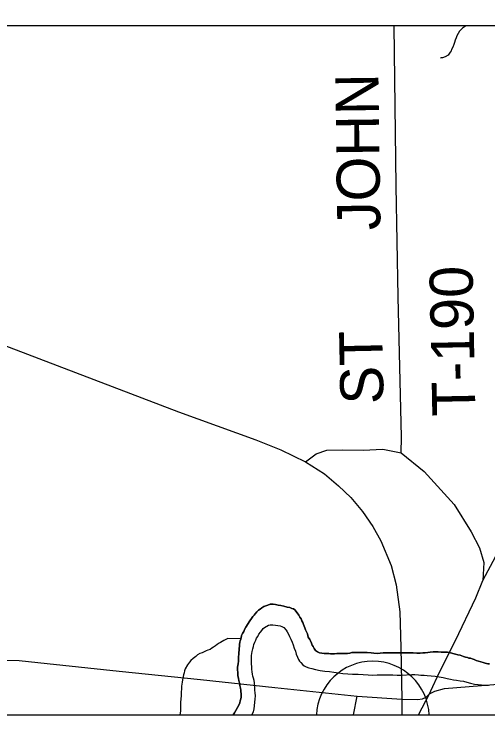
# Model space of a CAD drawing. Extents: x 0 to 34, y 0 to 22.
# Drawn here: x 3.825 to 4.449, y 14.1 to 15.024 of the extents above; entities that cross this region are included whole.
import ezdxf

# ---------------------------------------------------------------- set-up
doc = ezdxf.new("R2010")
doc.units = 0
for name, color, linetype in [('Default', 7, 'Continuous'), ('GM_X_Corporation', 7, 'Continuous'), ('GM_X_County_Road', 7, 'Continuous'), ('GM_X_Interchange_Ramps', 7, 'Continuous'), ('GM_X_Major_River', 7, 'Continuous'), ('GM_X_Minor_River', 7, 'Continuous'), ('GM_X_State_Route', 7, 'Continuous'), ('GM_X_Township_Road', 7, 'Continuous'), ('GM_X_Township_Road_Text', 7, 'Continuous'), ('SH_Text', 7, 'Continuous')]:
    doc.layers.add(name, color=color, linetype=linetype)

msp = doc.modelspace()

# ---------------------------------------------------------------- linework, layer by layer
at = {"layer": 'Default'}
msp.add_line((4.2227, 14.09996), (4.37135, 14.09996), dxfattribs=at)
msp.add_arc((4.29702, 14.09646), 0.0744, 2.69021, 177.30979, dxfattribs=at)
at = {"layer": 'GM_X_Corporation'}
msp.add_lwpolyline([(2.1, 20.24562), (2.1, 14.09996), (8.03831, 14.09996), (8.03504, 14.24979), (8.03488, 14.25722), (8.02966, 14.49633), (8.02618, 14.65547), (8.01532, 15.22729), (7.992, 16.45338)], dxfattribs=at)
msp.add_lwpolyline([(3.69009, 15.2048), (3.5209, 15.20411), (2.73663, 15.2014), (2.74225, 14.8151), (2.77525, 14.15375), (2.77611, 14.09996), (8.03831, 14.09996), (8.03504, 14.24979), (8.03488, 14.25722), (8.02966, 14.49633), (8.02618, 14.65547), (8.01532, 15.22729), (6.94963, 15.21339), (6.73943, 15.21199), (6.10258, 15.21454), (5.90994, 15.21376), (5.90994, 15.00852), (3.69009, 15.00852)], close=True, dxfattribs=at)
at = {"layer": 'GM_X_County_Road'}
for points in [[(4.37186, 14.12778), (4.37866, 14.13146), (4.39153, 14.13478), (4.45653, 14.14008), (4.51438, 14.14371), (4.54209, 14.14315), (4.55925, 14.14066), (4.57097, 14.13691), (4.58939, 14.12967), (4.60672, 14.12243), (4.62229, 14.11958), (4.68392, 14.13822), (4.80543, 14.17661), (4.84359, 14.18889), (4.8607, 14.19328), (4.88483, 14.19613), (5.40157, 14.20293), (5.82553, 14.20973), (6.23392, 14.21543), (6.32121, 14.21718), (6.41443, 14.21894), (6.67543, 14.22508), (6.98358, 14.22946)], [(3.43803, 14.13958), (3.55263, 14.15033), (3.69315, 14.16225), (3.77903, 14.17046), (3.81272, 14.17211), (3.83121, 14.1717), (3.86819, 14.168), (3.9631, 14.15773), (4.06993, 14.14663), (4.16814, 14.13636), (4.27647, 14.12494), (4.3352, 14.12095)], [(4.3352, 14.12095), (4.35607, 14.12023), (4.36266, 14.12104), (4.36712, 14.12344), (4.37186, 14.12778)]]:
    msp.add_lwpolyline(points, dxfattribs=at)
at = {"layer": 'GM_X_Interchange_Ramps'}
msp.add_line((4.35709, 14.09996), (4.37186, 14.12778), dxfattribs=at)
at = {"layer": 'GM_X_Major_River'}
for points in [[(4.32892, 14.18188), (4.32511, 14.18192), (4.32131, 14.18197), (4.31751, 14.18201), (4.31409, 14.18205), (4.31067, 14.18171), (4.30686, 14.18138), (4.30268, 14.18105), (4.2985, 14.18148), (4.29471, 14.18191), (4.28977, 14.18234), (4.28597, 14.18239), (4.28217, 14.18243), (4.27799, 14.18248), (4.2738, 14.18253), (4.26962, 14.1822), (4.26657, 14.18148), (4.26352, 14.18113), (4.2601, 14.1808), (4.25668, 14.18084), (4.25326, 14.18087), (4.24946, 14.18092), (4.24679, 14.18057), (4.24413, 14.18061), (4.24147, 14.18064), (4.23919, 14.18104), (4.23653, 14.18108), (4.23311, 14.18112), (4.23008, 14.18153), (4.22704, 14.18195), (4.22401, 14.18312), (4.22176, 14.18505), (4.21989, 14.18773), (4.21839, 14.19003), (4.21728, 14.19194), (4.21617, 14.19462), (4.21507, 14.19767), (4.21395, 14.19959), (4.21209, 14.20265), (4.211, 14.20684), (4.20951, 14.20952), (4.2084, 14.21219), (4.20767, 14.21486), (4.20656, 14.21716), (4.20582, 14.21944), (4.20471, 14.22174), (4.2036, 14.22403), (4.20249, 14.2267), (4.201, 14.229), (4.19951, 14.23168), (4.19727, 14.23475), (4.19427, 14.23858), (4.19238, 14.23975), (4.19049, 14.24053), (4.18785, 14.2417), (4.18405, 14.24212), (4.17988, 14.24331), (4.17571, 14.24412), (4.1723, 14.24492), (4.16889, 14.24573), (4.16585, 14.24614), (4.16395, 14.24616), (4.16167, 14.24581), (4.15861, 14.24471), (4.15594, 14.24398), (4.15365, 14.24287), (4.15097, 14.24138), (4.14867, 14.2395), (4.14637, 14.23801), (4.14444, 14.23613), (4.14213, 14.2335), (4.14059, 14.23162), (4.13904, 14.22974), (4.13711, 14.2271), (4.13518, 14.22408), (4.12975, 14.21579), (4.1282, 14.21277), (4.12703, 14.21012), (4.12547, 14.20748), (4.1243, 14.20483), (4.1235, 14.2018), (4.1231, 14.19991), (4.12231, 14.19763), (4.12191, 14.19574), (4.1215, 14.19308), (4.12147, 14.1908), (4.12105, 14.18739), (4.12102, 14.18511), (4.12061, 14.18283), (4.12058, 14.18017), (4.12016, 14.17676), (4.12013, 14.1741), (4.12009, 14.17106), (4.11967, 14.16726), (4.11886, 14.16309), (4.11881, 14.15929), (4.11915, 14.15587), (4.11948, 14.15206), (4.1202, 14.14825), (4.12054, 14.14521), (4.12126, 14.14178)], [(4.12126, 14.14178), (4.12054, 14.14521), (4.1202, 14.14825), (4.11948, 14.15206), (4.11915, 14.15587), (4.11881, 14.15929), (4.11886, 14.16309), (4.11967, 14.16726), (4.12009, 14.17106), (4.12013, 14.1741), (4.12016, 14.17676), (4.12058, 14.18017), (4.12061, 14.18283), (4.12102, 14.18511), (4.12105, 14.18739), (4.12147, 14.1908), (4.1215, 14.19308), (4.12191, 14.19574), (4.12231, 14.19763), (4.1231, 14.19991), (4.1235, 14.2018), (4.1243, 14.20483), (4.12547, 14.20748), (4.12703, 14.21012), (4.1282, 14.21277), (4.12975, 14.21579), (4.13518, 14.22408), (4.13711, 14.2271), (4.13904, 14.22974), (4.14059, 14.23162), (4.14213, 14.2335), (4.14444, 14.23613), (4.14637, 14.23801), (4.14867, 14.2395), (4.15097, 14.24138), (4.15365, 14.24287), (4.15594, 14.24398), (4.15861, 14.24471), (4.16167, 14.24581), (4.16395, 14.24616), (4.16585, 14.24614), (4.16889, 14.24573), (4.1723, 14.24492), (4.17571, 14.24412), (4.17988, 14.24331), (4.18405, 14.24212), (4.18785, 14.2417), (4.19049, 14.24053), (4.19238, 14.23975), (4.19427, 14.23858), (4.19727, 14.23475), (4.19951, 14.23168), (4.201, 14.229), (4.20249, 14.2267), (4.2036, 14.22403), (4.20471, 14.22174), (4.20582, 14.21944), (4.20656, 14.21716), (4.20767, 14.21486), (4.2084, 14.21219), (4.20951, 14.20952), (4.211, 14.20684), (4.21209, 14.20265), (4.21395, 14.19959), (4.21507, 14.19767), (4.21617, 14.19462), (4.21728, 14.19194), (4.21839, 14.19003), (4.21989, 14.18773), (4.22176, 14.18505), (4.22401, 14.18312), (4.22704, 14.18195), (4.23008, 14.18153), (4.23311, 14.18112), (4.23653, 14.18108), (4.23919, 14.18104), (4.24147, 14.18064), (4.24413, 14.18061), (4.24679, 14.18057), (4.24946, 14.18092), (4.25326, 14.18087), (4.25668, 14.18084), (4.2601, 14.1808), (4.26352, 14.18113), (4.26657, 14.18148), (4.26962, 14.1822), (4.2738, 14.18253), (4.27799, 14.18248), (4.28217, 14.18243), (4.28597, 14.18239), (4.28977, 14.18234), (4.29471, 14.18191), (4.2985, 14.18148), (4.30268, 14.18105), (4.30686, 14.18138), (4.31067, 14.18171), (4.31409, 14.18205), (4.31751, 14.18201), (4.32131, 14.18197), (4.32511, 14.18192), (4.32892, 14.18188)], [(4.13779, 14.09996), (4.13786, 14.10016), (4.13982, 14.10432), (4.141, 14.1081), (4.14143, 14.1119), (4.14187, 14.11683), (4.1423, 14.12101), (4.14235, 14.12519), (4.14201, 14.12899), (4.14168, 14.1328), (4.14173, 14.13698), (4.14141, 14.1423), (4.14069, 14.14535), (4.13997, 14.1484), (4.13924, 14.15107), (4.13851, 14.15373), (4.13817, 14.15678), (4.13783, 14.1602), (4.13749, 14.16401), (4.13715, 14.16705), (4.13719, 14.17085), (4.13724, 14.17465), (4.13729, 14.17845), (4.13811, 14.18376), (4.13891, 14.18718), (4.13971, 14.1902), (4.1405, 14.19286), (4.14168, 14.19588), (4.14285, 14.19853), (4.14402, 14.20118), (4.14557, 14.20344), (4.14713, 14.20646), (4.14906, 14.2091), (4.15099, 14.21135), (4.15254, 14.21399), (4.15446, 14.21511), (4.15982, 14.21847), (4.16172, 14.21883), (4.16362, 14.2188), (4.16552, 14.21878), (4.16894, 14.21836), (4.17198, 14.21794), (4.17501, 14.21753), (4.17728, 14.21674), (4.17993, 14.21519), (4.18292, 14.21173), (4.18442, 14.20944), (4.1859, 14.20638), (4.18738, 14.20332), (4.18924, 14.19988), (4.19072, 14.19606), (4.19219, 14.19224)], [(4.13779, 14.09996), (4.13786, 14.10016), (4.13982, 14.10432), (4.141, 14.1081), (4.14143, 14.1119), (4.14187, 14.11683), (4.1423, 14.12101), (4.14235, 14.12519), (4.14201, 14.12899), (4.14168, 14.1328), (4.14173, 14.13698), (4.14141, 14.1423), (4.14069, 14.14535), (4.13997, 14.1484), (4.13924, 14.15107), (4.13851, 14.15373), (4.13817, 14.15678), (4.13783, 14.1602), (4.13749, 14.16401), (4.13715, 14.16705), (4.13719, 14.17085), (4.13724, 14.17465), (4.13729, 14.17845), (4.13811, 14.18376), (4.13891, 14.18718), (4.13971, 14.1902), (4.1405, 14.19286), (4.14168, 14.19588), (4.14285, 14.19853), (4.14402, 14.20118), (4.14557, 14.20344), (4.14713, 14.20646), (4.14906, 14.2091), (4.15099, 14.21135), (4.15254, 14.21399), (4.15446, 14.21511), (4.15982, 14.21847), (4.16172, 14.21883), (4.16362, 14.2188), (4.16552, 14.21878), (4.16894, 14.21836), (4.17198, 14.21794), (4.17501, 14.21753), (4.17728, 14.21674), (4.17993, 14.21519), (4.18292, 14.21173), (4.18442, 14.20944), (4.1859, 14.20638), (4.18738, 14.20332), (4.18924, 14.19988), (4.19072, 14.19606), (4.19219, 14.19224)], [(4.19219, 14.19224), (4.19366, 14.18805), (4.19514, 14.18423), (4.19623, 14.18003), (4.1977, 14.17621), (4.19919, 14.17316), (4.20068, 14.17086), (4.20218, 14.16894), (4.2048, 14.16625), (4.20669, 14.16471), (4.20933, 14.16354), (4.21274, 14.16198), (4.21691, 14.16117), (4.22146, 14.15997), (4.2279, 14.15876), (4.23397, 14.15792), (4.24005, 14.15709), (4.24574, 14.15626), (4.25181, 14.15543), (4.2575, 14.1546), (4.26396, 14.15415), (4.27042, 14.15369), (4.27764, 14.1536), (4.28448, 14.15352), (4.29094, 14.15307), (4.29625, 14.15262), (4.30272, 14.15293), (4.30766, 14.15287), (4.31336, 14.1528), (4.31868, 14.15274), (4.32362, 14.15268), (4.32895, 14.15261), (4.33464, 14.15255), (4.34834, 14.15315), (4.35252, 14.1531), (4.35707, 14.15266), (4.3605, 14.15262), (4.36468, 14.15257), (4.36885, 14.15214), (4.37379, 14.1517), (4.37911, 14.15126), (4.38442, 14.15044), (4.38972, 14.14923), (4.39503, 14.14803), (4.39958, 14.14722), (4.40338, 14.14641), (4.40717, 14.14598), (4.41211, 14.14517), (4.41628, 14.14436), (4.42082, 14.14316), (4.42575, 14.14196), (4.43106, 14.14076), (4.43561, 14.13995), (4.44017, 14.13951), (4.44473, 14.13946), (4.44929, 14.13941)], [(4.19219, 14.19224), (4.19366, 14.18805), (4.19514, 14.18423), (4.19623, 14.18003), (4.1977, 14.17621), (4.19919, 14.17316), (4.20068, 14.17086), (4.20218, 14.16894), (4.2048, 14.16625), (4.20669, 14.16471), (4.20933, 14.16354), (4.21274, 14.16198), (4.21691, 14.16117), (4.22146, 14.15997), (4.2279, 14.15876), (4.23397, 14.15792), (4.24005, 14.15709), (4.24574, 14.15626), (4.25181, 14.15543), (4.2575, 14.1546), (4.26396, 14.15415), (4.27042, 14.15369), (4.27764, 14.1536), (4.28448, 14.15352), (4.29094, 14.15307), (4.29625, 14.15262), (4.30272, 14.15293), (4.30766, 14.15287), (4.31336, 14.1528), (4.31868, 14.15274), (4.32362, 14.15268), (4.32895, 14.15261), (4.33464, 14.15255), (4.34834, 14.15315), (4.35252, 14.1531), (4.35707, 14.15266), (4.3605, 14.15262), (4.36468, 14.15257), (4.36885, 14.15214), (4.37379, 14.1517), (4.37911, 14.15126), (4.38442, 14.15044), (4.38972, 14.14923), (4.39503, 14.14803), (4.39958, 14.14722), (4.40338, 14.14641), (4.40717, 14.14598), (4.41211, 14.14517), (4.41628, 14.14436), (4.42082, 14.14316), (4.42575, 14.14196), (4.43106, 14.14076), (4.43561, 14.13995), (4.44017, 14.13951), (4.44473, 14.13946), (4.44929, 14.13941)], [(4.45077, 14.16751), (4.44849, 14.16754), (4.44507, 14.16834), (4.44242, 14.16913), (4.43939, 14.16993), (4.43636, 14.17072), (4.43333, 14.1719), (4.43069, 14.17307), (4.42804, 14.17386), (4.42576, 14.17465), (4.42349, 14.17505), (4.4216, 14.17584), (4.41932, 14.17624), (4.41667, 14.17704), (4.4144, 14.17782), (4.41213, 14.17861), (4.4091, 14.17941), (4.40606, 14.1802), (4.39772, 14.1822), (4.39545, 14.18261), (4.39279, 14.18264), (4.38975, 14.18268), (4.38709, 14.18271), (4.38329, 14.18313), (4.38025, 14.18317), (4.37645, 14.18321), (4.37264, 14.18288), (4.3696, 14.18253), (4.36617, 14.18181), (4.36275, 14.18186), (4.35932, 14.18152), (4.35514, 14.18157), (4.35021, 14.18201), (4.34488, 14.18169), (4.33804, 14.18177), (4.33348, 14.18183), (4.32892, 14.18188)], [(4.32892, 14.18188), (4.33348, 14.18183), (4.33804, 14.18177), (4.34488, 14.18169), (4.35021, 14.18201), (4.35514, 14.18157), (4.35932, 14.18152), (4.36275, 14.18186), (4.36617, 14.18181), (4.3696, 14.18253), (4.37264, 14.18288), (4.37645, 14.18321), (4.38025, 14.18317), (4.38329, 14.18313), (4.38709, 14.18271), (4.38975, 14.18268), (4.39279, 14.18264), (4.39545, 14.18261), (4.39772, 14.1822), (4.40606, 14.1802), (4.4091, 14.17941), (4.41213, 14.17861), (4.4144, 14.17782), (4.41667, 14.17704), (4.41932, 14.17624), (4.4216, 14.17584), (4.42349, 14.17505), (4.42576, 14.17465), (4.42804, 14.17386), (4.43069, 14.17307), (4.43333, 14.1719), (4.43636, 14.17072), (4.43939, 14.16993), (4.44242, 14.16913), (4.44507, 14.16834), (4.44849, 14.16754), (4.45077, 14.16751)], [(4.12126, 14.14178), (4.12198, 14.13873), (4.1227, 14.1353), (4.12305, 14.13264), (4.1234, 14.13035), (4.12376, 14.12807), (4.12373, 14.12579), (4.1237, 14.12351), (4.12329, 14.12123), (4.1225, 14.11858), (4.12171, 14.11593), (4.12053, 14.11291), (4.11897, 14.10988), (4.11664, 14.10573), (4.11471, 14.10271), (4.11313, 14.09996)], [(4.11313, 14.09996), (4.11471, 14.10271), (4.11664, 14.10573), (4.11897, 14.10988), (4.12053, 14.11291), (4.12171, 14.11593), (4.1225, 14.11858), (4.12329, 14.12123), (4.1237, 14.12351), (4.12373, 14.12579), (4.12376, 14.12807), (4.1234, 14.13035), (4.12305, 14.13264), (4.1227, 14.1353), (4.12198, 14.13873), (4.12126, 14.14178)]]:
    msp.add_lwpolyline(points, dxfattribs=at)
at = {"layer": 'GM_X_Minor_River'}
for points in [[(4.42012, 15.00852), (4.41907, 15.00783), (4.41524, 15.00522), (4.41331, 15.00334), (4.41101, 15.00147), (4.40945, 14.99844), (4.40789, 14.99504), (4.40672, 14.99239), (4.40554, 14.98937), (4.40475, 14.98634), (4.40357, 14.98369), (4.40239, 14.98028), (4.40083, 14.97726), (4.40005, 14.97537), (4.39889, 14.97348), (4.39618, 14.96972), (4.39235, 14.96748), (4.38891, 14.966), (4.38663, 14.96603), (4.38663, 14.96565), (4.38663, 14.96603)], [(4.12323, 14.20051), (4.106, 14.20087), (4.10256, 14.19901), (4.10065, 14.19827), (4.09644, 14.19566), (4.09453, 14.19454), (4.09223, 14.19305), (4.08992, 14.19118), (4.08724, 14.18931), (4.08494, 14.18782), (4.08264, 14.18632), (4.07997, 14.18521), (4.07768, 14.18448), (4.075, 14.18299), (4.07232, 14.18188), (4.06927, 14.18078), (4.06621, 14.1793), (4.0639, 14.17704), (4.06045, 14.17442), (4.05738, 14.1718), (4.05545, 14.16954), (4.05313, 14.16615), (4.05003, 14.16087), (4.04923, 14.15822), (4.04844, 14.15557), (4.04765, 14.15291), (4.04724, 14.15064), (4.04683, 14.14836), (4.04643, 14.14609), (4.04601, 14.14305), (4.04519, 14.13812), (4.04514, 14.13432), (4.04471, 14.13015), (4.04466, 14.12559), (4.04422, 14.12065), (4.04379, 14.11686), (4.04376, 14.1142), (4.04371, 14.11002), (4.04365, 14.10508), (4.04283, 14.10015), (4.04283, 14.09996)]]:
    msp.add_lwpolyline(points, dxfattribs=at)
at = {"layer": 'GM_X_State_Route'}
msp.add_line((4.3352, 14.12095), (4.33547, 14.09996), dxfattribs=at)
for points in [[(3.79354, 14.59411), (4.04114, 14.49969), (4.14309, 14.46267), (4.17583, 14.44966), (4.20849, 14.43368), (4.23354, 14.418), (4.25207, 14.40209), (4.26789, 14.3867), (4.28362, 14.36806), (4.29701, 14.34826), (4.3075, 14.32962), (4.32106, 14.29707), (4.32764, 14.27163), (4.33269, 14.23588), (4.33378, 14.18894), (4.3352, 14.12095)], [(4.37186, 14.12778), (4.37365, 14.13172), (4.38423, 14.15539), (4.40597, 14.19834), (4.43292, 14.2543), (4.44213, 14.27733), (4.45893, 14.30908)], [(4.3352, 14.12095), (4.35607, 14.12023), (4.36266, 14.12104), (4.36712, 14.12344), (4.37186, 14.12778)]]:
    msp.add_lwpolyline(points, dxfattribs=at)
at = {"layer": 'GM_X_Township_Road'}
msp.add_line((4.27159, 14.09996), (4.27647, 14.12494), dxfattribs=at)
for points in [[(4.33424, 14.44533), (4.33468, 14.46633), (4.33025, 14.65127), (4.32792, 14.7971), (4.32508, 15.00852)], [(4.20849, 14.43368), (4.22253, 14.44437), (4.2365, 14.44919), (4.25672, 14.44966), (4.28416, 14.44919), (4.31016, 14.45015), (4.33424, 14.44533), (4.36457, 14.42078), (4.38672, 14.3967), (4.40405, 14.37745), (4.42668, 14.34133), (4.43775, 14.32015), (4.44305, 14.30089), (4.44213, 14.27733)]]:
    msp.add_lwpolyline(points, dxfattribs=at)
at = {"layer": 'SH_Text'}
msp.add_lwpolyline([(3.69009, 15.72564), (5.90994, 15.72564), (5.90994, 15.00852), (3.69009, 15.00852)], close=True, dxfattribs=at)

# ---------------------------------------------------------------- texts
at = {"layer": 'GM_X_Township_Road_Text'}
for s, rotation, p in [('JOHN', 90.77033, (4.30717, 14.73926)), ('T-190', 91.13002, (4.43229, 14.49411)), ('ST', 91.18055, (4.31134, 14.50994))]:
    msp.add_text(s, height=0.056818, rotation=rotation, dxfattribs=at).set_placement(p)

doc.saveas('drawing.dxf')
